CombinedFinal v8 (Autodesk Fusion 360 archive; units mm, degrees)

design "CombinedFinal" references "ThreadCatcher", "Spool", "17HS19-2004S1"
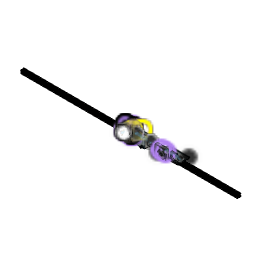
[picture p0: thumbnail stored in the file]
description: Part Number
part number: 5537T11_T-Slotted Framing
part number: 91290A221_Alloy Steel Socket Head Screw
part number: Space Allocation Model
part number: Motor_Bed
base_feature "Base Feature1"
move "Move1"
move "Move2"
move "Move3"
move "Move4"
component_insert "Component Insert1"
work_plane "WorkPlane1" AlongDistance 0
sketch "Stepper2020Side" plane through (0, 0, 0) normal (0, 0, 1) x axis (1, 0, 0)
  line L1 (21.0394, -25.4058) -> (-21.15, -25.4058)
  line L2 (21.0394, 35) -> (21.0394, -25.4058)
  line L3 (-21.15, 35) -> (21.0394, 35)
  line L4 (-21.15, -25.4058) -> (-21.15, 35)
  horizontal L1
  vertical L2
  horizontal L3
  vertical L4
extrude "Extrude2" new body blind 3
extrude "Extrude3" add to an object
extrude "Extrude4" add blind -6
extrude "Extrude5" add sketch "Stepper2020Side" to an object
base_feature "Base Feature1"
move "Move1"
position "Position1"
sketch "StepperSide" plane through (0, -20.4058, 0) normal (0, -1, 0) x axis (1, 0, 0)
  line L1 (16.9429, 17.1363) -> (-16.9429, 17.1363)
  line L2 (20.65, 20.8434) -> (16.9429, 17.1363)
  line L3 (20.65, 54.7291) -> (20.65, 20.8434)
  line L4 (16.9429, 58.4363) -> (20.65, 54.7291)
  line L5 (-16.9429, 58.4363) -> (16.9429, 58.4363)
  line L6 (-20.65, 54.7291) -> (-16.9429, 58.4363)
  line L7 (-20.65, 20.8434) -> (-20.65, 54.7291)
  line L8 (-16.9429, 17.1363) -> (-20.65, 20.8434)
  line L9 (21.15, 54.7291) -> (20.65, 54.7291)
  line L10 (20.65, 20.8434) -> (20.65, 54.7291)
  line L11 (20.65, 20.8434) -> (21.15, 20.8434)
  line L12 (21.15, 54.7291) -> (21.15, 20.8434)
  line L13 (-16.9429, 58.4363) -> (-17.15, 58.9363)
  line L14 (16.9429, 58.4363) -> (-16.9429, 58.4363)
  line L15 (16.9429, 58.4363) -> (16.9429, 58.9363)
  line L16 (-17.15, 58.9363) -> (16.9429, 58.9363)
  line L17 (17.2964, 58.7898) -> (16.9429, 58.4363)
  line L18 (16.9429, 58.4363) -> (16.9429, 58.9363)
  line L19 (17.2964, 58.7898) -> (16.9429, 58.4363)
  line L20 (17.2964, 58.7898) -> (16.9429, 58.4363)
  line L21 (20.65, 54.7291) -> (16.9429, 58.4363)
  line L22 (21.0036, 55.0827) -> (20.65, 54.7291)
  line L23 (17.2964, 58.7898) -> (21.0036, 55.0827)
  line L24 (21.0036, 55.0827) -> (20.65, 54.7291)
  line L25 (21.15, 54.7291) -> (20.65, 54.7291)
  line L26 (20.65, 20.8434) -> (16.9429, 17.1363)
  line L27 (17.2964, 16.7827) -> (16.9429, 17.1363)
  line L28 (21.0036, 20.4898) -> (17.2964, 16.7827)
  line L29 (20.65, 20.8434) -> (21.0036, 20.4898)
  line L30 (16.9429, 17.1363) -> (20.65, 20.8434)
  line L31 (20.65, 20.8434) -> (21.15, 20.8434)
  line L32 (20.65, 20.8434) -> (21.0036, 20.4898)
  line L33 (20.65, 20.8434) -> (21.15, 20.8434)
  line L34 (-16.9429, 17.1363) -> (-16.9429, 16.6363)
  line L35 (16.9429, 16.6363) -> (-16.9429, 16.6363)
  line L36 (16.9429, 16.6363) -> (16.9429, 17.1363)
  line L37 (-16.9429, 17.1363) -> (16.9429, 17.1363)
  line L38 (17.2964, 16.7827) -> (16.9429, 17.1363)
  line L39 (17.2964, 16.7827) -> (16.9429, 17.1363)
  line L40 (16.9429, 16.6363) -> (16.9429, 17.1363)
  line L41 (-21.0036, 20.4898) -> (-20.65, 20.8434)
  line L42 (-17.2964, 16.7827) -> (-21.0036, 20.4898)
  line L43 (-17.2964, 16.7827) -> (-16.9429, 17.1363)
  line L44 (-20.65, 20.8434) -> (-16.9429, 17.1363)
  line L45 (-16.9429, 17.1363) -> (-16.9429, 16.6363)
  line L46 (-17.2964, 16.7827) -> (-16.9429, 17.1363)
  line L47 (-20.65, 54.7291) -> (-21.15, 54.7291)
  line L48 (-21.15, 20.8434) -> (-21.15, 54.7291)
  line L49 (-21.15, 20.8434) -> (-20.65, 20.8434)
  line L50 (-20.65, 54.7291) -> (-20.65, 20.8434)
  line L51 (-21.0036, 20.4898) -> (-20.65, 20.8434)
  line L52 (-21.0036, 20.4898) -> (-20.65, 20.8434)
  line L53 (-21.15, 20.8434) -> (-20.65, 20.8434)
  line L54 (-21.0036, 55.0827) -> (-20.65, 54.7291)
  line L55 (-16.9429, 58.4363) -> (-20.65, 54.7291)
  line L56 (-16.9429, 58.4363) -> (-17.15, 58.9363)
  line L57 (-21.0036, 55.0827) -> (-17.15, 58.9363)
  line L58 (-21.0036, 55.0827) -> (-20.65, 54.7291)
  line L59 (-20.65, 54.7291) -> (-21.15, 54.7291)
  circle C1 centre (0, 37.7863) radius 16
  circle C2 centre (15.5, 53.2863) radius 1.25
  circle C3 centre (-15.5, 53.2863) radius 1.25
  circle C4 centre (-15.5, 22.2863) radius 1.25
  circle C5 centre (15.5, 22.2863) radius 1.25
  arc A1 centre (16.9429, 58.4363) radius 0.5 clockwise from (16.9429, 58.9363) to (17.2964, 58.7898)
  arc A2 centre (20.65, 54.7291) radius 0.5 clockwise from (21.0036, 55.0827) to (21.15, 54.7291)
  arc A3 centre (20.65, 20.8434) radius 0.5 clockwise from (21.15, 20.8434) to (21.0036, 20.4898)
  arc A4 centre (16.9429, 17.1363) radius 0.5 clockwise from (17.2964, 16.7827) to (16.9429, 16.6363)
  arc A5 centre (-16.9429, 17.1363) radius 0.5 clockwise from (-16.9429, 16.6363) to (-17.2964, 16.7827)
  arc A6 centre (-20.65, 20.8434) radius 0.5 clockwise from (-21.0036, 20.4898) to (-21.15, 20.8434)
  arc A7 centre (-20.65, 54.7291) radius 0.5 clockwise from (-21.15, 54.7291) to (-21.0036, 55.0827)
extrude "Extrude7" new body sketch "StepperSide" along normal blind 3
sketch "StepperBottom" plane through (0, 0, 16.6363) normal (0, 0, -1) x axis (1, 0, 0)
  line L1 (16.9429, 20.4058) -> (-16.9429, 20.4058)
  line L2 (16.9429, 23.4058) -> (16.9429, 20.4058)
  line L3 (-16.9429, 23.4058) -> (16.9429, 23.4058)
  line L4 (-16.9429, 20.4058) -> (-16.9429, 23.4058)
  line L5 (16.9429, 20.4058) -> (17.2964, 20.4058)
  line L6 (17.2964, 23.4058) -> (17.2964, 20.4058)
  line L7 (16.9429, 23.4058) -> (17.2964, 23.4058)
  line L8 (16.9429, 20.4058) -> (16.9429, 23.4058)
  line L9 (21.0036, 20.4058) -> (17.2964, 20.4058)
  line L10 (21.0036, 23.4058) -> (21.0036, 20.4058)
  line L11 (17.2964, 23.4058) -> (21.0036, 23.4058)
  line L12 (17.2964, 20.4058) -> (17.2964, 23.4058)
  line L13 (21.0036, 20.4058) -> (21.15, 20.4058)
  line L14 (21.15, 23.4058) -> (21.15, 20.4058)
  line L15 (21.0036, 23.4058) -> (21.15, 23.4058)
  line L16 (21.0036, 20.4058) -> (21.0036, 23.4058)
  line L17 (-17.2964, 20.4058) -> (-16.9429, 20.4058)
  line L18 (-16.9429, 23.4058) -> (-16.9429, 20.4058)
  line L19 (-17.2964, 23.4058) -> (-16.9429, 23.4058)
  line L20 (-17.2964, 20.4058) -> (-17.2964, 23.4058)
  line L21 (-17.2964, 20.4058) -> (-21.0036, 20.4058)
  line L22 (-17.2964, 23.4058) -> (-17.2964, 20.4058)
  line L23 (-21.0036, 23.4058) -> (-17.2964, 23.4058)
  line L24 (-21.0036, 20.4058) -> (-21.0036, 23.4058)
  line L25 (-21.15, 20.4058) -> (-21.0036, 20.4058)
  line L26 (-21.0036, 23.4058) -> (-21.0036, 20.4058)
  line L27 (-21.15, 23.4058) -> (-21.0036, 23.4058)
  line L28 (-21.15, 20.4058) -> (-21.15, 23.4058)
extrude "Extrude8" new body sketch "StepperBottom" to an object Side2Offset 0
extrude "Extrude9" add sketch "StepperBottom" profile of L2 L4 L5 L6 L7 L8 L9 L10 L11 L12 L13 L14 L15 L16 L17 L18 L19 L20 L21 L22 L23 L24 L25 L26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 against normal blind 4.5
extrude "Extrude10" new body sketch "Stepper2020Side" to an object
move "Move2"
position "Position2"
move "Move3"
component_insert "Component Insert2"
position "Position3"
sketch "Sketch8" plane through (0, 0, 16.6363) normal (0, 0, 1) x axis (-1, 0, 0)
  line L1 (-21.0394, 25.4058) -> (21.15, 25.4058)
  line L2 (-21.0394, -32) -> (-21.0394, 25.4058)
  line L3 (21.15, -32) -> (-21.0394, -32)
  line L4 (21.15, 25.4058) -> (21.15, -32)
  circle C1 centre (0, 0) radius 2.5
  point P1 (0, 0)
  point P6 (0, 0)
  coincident P1 P6
  dimension "d24" diameter C1 = 5
position "Position4"
hole "Hole1" HoleDiameter 5.5 TipAngle 118 CBDepth 5 CBDiameter 10
component_insert "Component Insert3"
base_feature "Base Feature1"
base_feature "Base Feature1"
base_feature "Base Feature1"
position "Position5"
sketch "Sketch9" plane through (0, 0, 16.6363) normal (0, 0, 1) x axis (-1, 0, 0)
sketch "Sketch10" plane through (0, 0, 16.6363) normal (0, 0, 1) x axis (-1, 0, 0)
  line L1 (-21.0394, 25.4058) -> (21.15, 25.4058)
  line L2 (21.15, -32) -> (-21.0394, -32)
  line L3 (21.15, 25.4058) -> (21.15, -32)
  line L4 (-40.0394, 25.4058) -> (-21.0394, 25.4058)
  line L5 (-40.0394, 28.4058) -> (-40.0394, 25.4058)
  line L6 (-21.0394, 28.4058) -> (-40.0394, 28.4058)
  line L7 (-21.0394, 25.4058) -> (-21.0394, 28.4058)
  circle C1 centre (0.0553, 0) radius 5
  point P4 (-21.0394, 25.4058)
  point P7 (-21.0394, 25.4058)
  horizontal L4
  vertical L5
  horizontal L6
  vertical L7
  coincident P4 P7
sketch "Sketch12" plane through (0, 0, 0) normal (0, 1, 0) x axis (1, 0, 0)
sketch "Sketch13" plane through (0, -40.1098, 0) normal (0, -1, 0) x axis (1, 0, 0)
  circle C1 centre (69.4158, 38.2803) radius 20.734
  circle C2 centre (69.4158, 38.2803) radius 7
  circle C3 centre (69.4158, 38.2803) radius 6.5
  dimension "d40" diameter C2 = 14
extrude "Extrude11" new body sketch "Sketch13" profile of C2 against normal blind 30 and along normal blind 10
sketch "Sketch15" plane through (0, 0, 10) normal (0, 0, 1) x axis (-1, 0, 0)
  line L1 (-600, -8.25) -> (-600, -3)
  line L2 (619.2, -8.25) -> (-600, -8.25)
  line L3 (619.2, -3) -> (619.2, -8.25)
  line L4 (-600, -3) -> (619.2, -3)
  line L5 (-50, 25) -> (-50, -17)
  line L6 (-117, -17) -> (-50, -17)
  line L7 (-117, 25) -> (-117, -17)
  line L8 (-50, 25) -> (-117, 25)
  line L9 (-50, -17) -> (-50, 25)
  line L10 (-50, 10.1125) -> (-117, 10.1125)
  line L11 (-50, 25) -> (-50, 10.1125)
  line L12 (-117, 25) -> (-50, 25)
  line L13 (-117, 10.1125) -> (-117, 25)
  point P11 (-117, 10.1125)
  point P6 (-50, 25)
  point P7 (-50, -17)
  horizontal L6
  vertical L7
  horizontal L8
  vertical L9
  horizontal L10
  vertical L11
  horizontal L12
  vertical L13
  coincident L7 P11
  dimension "d46" distance P6 P7 = 42
move_face "MoveFace1"
position "Position8"
extrude "Extrude12" new body sketch "Sketch15" profile of L2 L4 L5 to an object
extrude "Extrude14" new body sketch "Sketch15" profile of L2 L4 L5 to an object
extrude "Extrude15" new body sketch "Sketch15" profile of L5 L7 L8 L9 L10 L11 L12 L13 along normal blind 55
position "Position9"
hole "Hole1" HoleDepth 8 HoleDiameter 4.234 TipAngle 118 CBDepth 1 CBDiameter 6.6
sketch "Sketch16" plane through (0, 0, 16.6363) normal (0, 0, 1) x axis (-1, 0, 0)
  line L1 (-187, 10.1125) -> (-120, 10.1125)
  line L2 (-187, -17) -> (-187, 10.1125)
  line L3 (-120, -17) -> (-187, -17)
  line L4 (-120, 10.1125) -> (-120, -17)
  circle C1 centre (-155, 0) radius 2.5
  dimension "d66" diameter C1 = 5
position "Position11"
base_feature "Base Feature1"
move "Move1"
move "Move2"
move "Move3"
move "Move4"
component_insert "Component Insert1"
work_plane "WorkPlane1" AlongDistance 0 named "d1_1"
sketch "Stepper2020Side" plane through (0, 0, 0) normal (0, 0, 1) x axis (1, 0, 0)
  line L1 (21.0394, -25.4058) -> (-21.15, -25.4058)
  line L2 (21.0394, 35) -> (21.0394, -25.4058)
  line L3 (-21.15, 35) -> (21.0394, 35)
  line L4 (-21.15, -25.4058) -> (-21.15, 35)
  horizontal L1
  vertical L2
  horizontal L3
  vertical L4
base_feature "Base Feature1"
position "Position1"
sketch "StepperSide" plane through (0, -20.4058, 0) normal (0, -1, 0) x axis (1, 0, 0)
  line L1 (16.9429, 17.1363) -> (-16.9429, 17.1363)
  line L2 (20.65, 20.8434) -> (16.9429, 17.1363)
  line L3 (20.65, 54.7291) -> (20.65, 20.8434)
  line L4 (16.9429, 58.4363) -> (20.65, 54.7291)
  line L5 (-16.9429, 58.4363) -> (16.9429, 58.4363)
  line L6 (-20.65, 54.7291) -> (-16.9429, 58.4363)
  line L7 (-20.65, 20.8434) -> (-20.65, 54.7291)
  line L8 (-16.9429, 17.1363) -> (-20.65, 20.8434)
  line L9 (21.15, 54.7291) -> (20.65, 54.7291)
  line L10 (20.65, 20.8434) -> (20.65, 54.7291)
  line L11 (20.65, 20.8434) -> (21.15, 20.8434)
  line L12 (21.15, 54.7291) -> (21.15, 20.8434)
  line L13 (-16.9429, 58.4363) -> (-17.15, 58.9363)
  line L14 (16.9429, 58.4363) -> (-16.9429, 58.4363)
  line L15 (16.9429, 58.4363) -> (16.9429, 58.9363)
  line L16 (-17.15, 58.9363) -> (16.9429, 58.9363)
  line L17 (17.2964, 58.7898) -> (16.9429, 58.4363)
  line L18 (16.9429, 58.4363) -> (16.9429, 58.9363)
  line L19 (17.2964, 58.7898) -> (16.9429, 58.4363)
  line L20 (17.2964, 58.7898) -> (16.9429, 58.4363)
  line L21 (20.65, 54.7291) -> (16.9429, 58.4363)
  line L22 (21.0036, 55.0827) -> (20.65, 54.7291)
  line L23 (17.2964, 58.7898) -> (21.0036, 55.0827)
  line L24 (21.0036, 55.0827) -> (20.65, 54.7291)
  line L25 (21.15, 54.7291) -> (20.65, 54.7291)
  line L26 (20.65, 20.8434) -> (16.9429, 17.1363)
  line L27 (17.2964, 16.7827) -> (16.9429, 17.1363)
  line L28 (21.0036, 20.4898) -> (17.2964, 16.7827)
  line L29 (20.65, 20.8434) -> (21.0036, 20.4898)
  line L30 (16.9429, 17.1363) -> (20.65, 20.8434)
  line L31 (20.65, 20.8434) -> (21.15, 20.8434)
  line L32 (20.65, 20.8434) -> (21.0036, 20.4898)
  line L33 (20.65, 20.8434) -> (21.15, 20.8434)
  line L34 (-16.9429, 17.1363) -> (-16.9429, 16.6363)
  line L35 (16.9429, 16.6363) -> (-16.9429, 16.6363)
  line L36 (16.9429, 16.6363) -> (16.9429, 17.1363)
  line L37 (-16.9429, 17.1363) -> (16.9429, 17.1363)
  line L38 (17.2964, 16.7827) -> (16.9429, 17.1363)
  line L39 (17.2964, 16.7827) -> (16.9429, 17.1363)
  line L40 (16.9429, 16.6363) -> (16.9429, 17.1363)
  line L41 (-21.0036, 20.4898) -> (-20.65, 20.8434)
  line L42 (-17.2964, 16.7827) -> (-21.0036, 20.4898)
  line L43 (-17.2964, 16.7827) -> (-16.9429, 17.1363)
  line L44 (-20.65, 20.8434) -> (-16.9429, 17.1363)
  line L45 (-16.9429, 17.1363) -> (-16.9429, 16.6363)
  line L46 (-17.2964, 16.7827) -> (-16.9429, 17.1363)
  line L47 (-20.65, 54.7291) -> (-21.15, 54.7291)
  line L48 (-21.15, 20.8434) -> (-21.15, 54.7291)
  line L49 (-21.15, 20.8434) -> (-20.65, 20.8434)
  line L50 (-20.65, 54.7291) -> (-20.65, 20.8434)
  line L51 (-21.0036, 20.4898) -> (-20.65, 20.8434)
  line L52 (-21.0036, 20.4898) -> (-20.65, 20.8434)
  line L53 (-21.15, 20.8434) -> (-20.65, 20.8434)
  line L54 (-21.0036, 55.0827) -> (-20.65, 54.7291)
  line L55 (-16.9429, 58.4363) -> (-20.65, 54.7291)
  line L56 (-16.9429, 58.4363) -> (-17.15, 58.9363)
  line L57 (-21.0036, 55.0827) -> (-17.15, 58.9363)
  line L58 (-21.0036, 55.0827) -> (-20.65, 54.7291)
  line L59 (-20.65, 54.7291) -> (-21.15, 54.7291)
  circle C1 centre (0, 37.7863) radius 16
  circle C2 centre (15.5, 53.2863) radius 1.25
  circle C3 centre (-15.5, 53.2863) radius 1.25
  circle C4 centre (-15.5, 22.2863) radius 1.25
  circle C5 centre (15.5, 22.2863) radius 1.25
  arc A1 centre (16.9429, 58.4363) radius 0.5 clockwise from (16.9429, 58.9363) to (17.2964, 58.7898)
  arc A2 centre (20.65, 54.7291) radius 0.5 clockwise from (21.0036, 55.0827) to (21.15, 54.7291)
  arc A3 centre (20.65, 20.8434) radius 0.5 clockwise from (21.15, 20.8434) to (21.0036, 20.4898)
  arc A4 centre (16.9429, 17.1363) radius 0.5 clockwise from (17.2964, 16.7827) to (16.9429, 16.6363)
  arc A5 centre (-16.9429, 17.1363) radius 0.5 clockwise from (-16.9429, 16.6363) to (-17.2964, 16.7827)
  arc A6 centre (-20.65, 20.8434) radius 0.5 clockwise from (-21.0036, 20.4898) to (-21.15, 20.8434)
  arc A7 centre (-20.65, 54.7291) radius 0.5 clockwise from (-21.15, 54.7291) to (-21.0036, 55.0827)
extrude "Extrude7" new body sketch "StepperSide" along normal blind 3 named "d14_1"
sketch "StepperBottom" plane through (0, 0, 16.6363) normal (0, 0, -1) x axis (1, 0, 0)
  line L1 (16.9429, 20.4058) -> (-16.9429, 20.4058)
  line L2 (16.9429, 23.4058) -> (16.9429, 20.4058)
  line L3 (-16.9429, 23.4058) -> (16.9429, 23.4058)
  line L4 (-16.9429, 20.4058) -> (-16.9429, 23.4058)
  line L5 (16.9429, 20.4058) -> (17.2964, 20.4058)
  line L6 (17.2964, 23.4058) -> (17.2964, 20.4058)
  line L7 (16.9429, 23.4058) -> (17.2964, 23.4058)
  line L8 (16.9429, 20.4058) -> (16.9429, 23.4058)
  line L9 (21.0036, 20.4058) -> (17.2964, 20.4058)
  line L10 (21.0036, 23.4058) -> (21.0036, 20.4058)
  line L11 (17.2964, 23.4058) -> (21.0036, 23.4058)
  line L12 (17.2964, 20.4058) -> (17.2964, 23.4058)
  line L13 (21.0036, 20.4058) -> (21.15, 20.4058)
  line L14 (21.15, 23.4058) -> (21.15, 20.4058)
  line L15 (21.0036, 23.4058) -> (21.15, 23.4058)
  line L16 (21.0036, 20.4058) -> (21.0036, 23.4058)
  line L17 (-17.2964, 20.4058) -> (-16.9429, 20.4058)
  line L18 (-16.9429, 23.4058) -> (-16.9429, 20.4058)
  line L19 (-17.2964, 23.4058) -> (-16.9429, 23.4058)
  line L20 (-17.2964, 20.4058) -> (-17.2964, 23.4058)
  line L21 (-17.2964, 20.4058) -> (-21.0036, 20.4058)
  line L22 (-17.2964, 23.4058) -> (-17.2964, 20.4058)
  line L23 (-21.0036, 23.4058) -> (-17.2964, 23.4058)
  line L24 (-21.0036, 20.4058) -> (-21.0036, 23.4058)
  line L25 (-21.15, 20.4058) -> (-21.0036, 20.4058)
  line L26 (-21.0036, 23.4058) -> (-21.0036, 20.4058)
  line L27 (-21.15, 23.4058) -> (-21.0036, 23.4058)
  line L28 (-21.15, 20.4058) -> (-21.15, 23.4058)
extrude "Extrude8" new body sketch "StepperBottom" to an object Side2Offset 0 named "d18_1"
extrude "Extrude9" add sketch "StepperBottom" profile of L2 L4 L5 L6 L7 L8 L9 L10 L11 L12 L13 L14 L15 L16 L17 L18 L19 L20 L21 L22 L23 L24 L25 L26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 against normal blind 4.5 named "d20_1"
extrude "Extrude10" new body sketch "Stepper2020Side" to an object
move "Move2"
position "Position2"
move "Move3"
combine "Combine1"
position "Position3"
sketch "Sketch8" plane through (0, 0, 16.6363) normal (0, 0, 1) x axis (-1, 0, 0)
  line L1 (-21.0394, 25.4058) -> (21.15, 25.4058)
  line L2 (-21.0394, -32) -> (-21.0394, 25.4058)
  line L3 (21.15, -32) -> (-21.0394, -32)
  line L4 (21.15, 25.4058) -> (21.15, -32)
  circle C1 centre (0, 0) radius 2.5
  point P1 (0, 0)
  point P6 (0, 0)
  coincident P1 P6
  dimension "d24_1" diameter C1 = 5
position "Position4"
hole "Hole1" HoleDiameter 5.5 named "d25_1" TipAngle 118 named "d26_1" CBDepth 5 named "d27_1" CBDiameter 10 named "d28_1"
sketch "Sketch10" plane through (0, 0, 16.6363) normal (0, 0, 1) x axis (-1, 0, 0)
  line L1 (-21.0394, 25.4058) -> (21.15, 25.4058)
  line L2 (21.15, -32) -> (-21.0394, -32)
  line L3 (21.15, 25.4058) -> (21.15, -32)
  line L4 (-40.0394, 25.4058) -> (-21.0394, 25.4058)
  line L5 (-40.0394, 28.4058) -> (-40.0394, 25.4058)
  line L6 (-21.0394, 28.4058) -> (-40.0394, 28.4058)
  line L7 (-21.0394, 25.4058) -> (-21.0394, 28.4058)
  circle C1 centre (0.0553, 0) radius 5
  point P4 (-21.0394, 25.4058)
  point P7 (-21.0394, 25.4058)
  horizontal L4
  vertical L5
  horizontal L6
  vertical L7
  coincident P4 P7
move_face "MoveFace3"
hole "Hole1" HoleDepth 8 named "d59_1" HoleDiameter 4.234 named "d60_1" TipAngle 118 named "d61_1" CBDepth 1 named "d62_1" CBDiameter 6.6 named "d63_1"
extrude "Extrude4" add of existing geometry blind 3
extrude "Extrude16" new body of existing geometry blind 3 named "d76_1"
sketch "Sketch17" plane through (0, -31.4058, 0) normal (0, -1, 0) x axis (1, 0, 0)
  line L1 (-21.15, 10) -> (-21.15, 54.7291)
  line L2 (21.15, 10) -> (-21.15, 10)
  line L3 (21.15, 54.7291) -> (21.15, 10)
  line L4 (17.2964, 58.7898) -> (21.0036, 55.0827)
  line L5 (-17.15, 58.9363) -> (16.9429, 58.9363)
  line L6 (-21.0036, 55.0827) -> (-17.15, 58.9363)
  arc A1 centre (20.65, 54.7291) radius 0.5 clockwise from (21.0036, 55.0827) to (21.15, 54.7291)
  arc A2 centre (16.9429, 58.4363) radius 0.5 clockwise from (16.9429, 58.9363) to (17.2964, 58.7898)
  arc A3 centre (-20.65, 54.7291) radius 0.5 clockwise from (-21.15, 54.7291) to (-21.0036, 55.0827)
  circle C1 centre (0, 37.7863) radius 16
  circle C2 centre (-15.5, 22.2863) radius 1.25
  circle C3 centre (15.5, 22.2863) radius 1.25
  circle C4 centre (-15.5, 53.2863) radius 1.25
  circle C5 centre (15.5, 53.2863) radius 1.25
hole "Hole2" HoleDepth 6 named "d78_1" HoleDiameter 2.529 named "d79_1" TipAngle 118 named "d80_1" CBDepth 1 named "d81_1" CBDiameter 2.782 named "d82_1"
combine "Combine1"
hole "Hole2" HoleDepth 10 named "d85_1" HoleDiameter 5.5 named "d86_1" TipAngle 118 named "d87_1" CBDepth 5 named "d88_1" CBDiameter 10 named "d89_1"
sketch "Sketch18" plane through (0, -31.4058, 0) normal (0, -1, 0) x axis (1, 0, 0)
  line L1 (-21.15, 10) -> (-21.15, 54.7291)
  line L2 (21.15, 10) -> (-21.15, 10)
  line L3 (21.15, 54.7291) -> (21.15, 10)
  line L4 (17.2964, 58.7898) -> (21.0036, 55.0827)
  line L5 (-17.15, 58.9363) -> (16.9429, 58.9363)
  line L6 (-21.0036, 55.0827) -> (-17.15, 58.9363)
  circle C1 centre (15.5, 22.2863) radius 1.391
  circle C2 centre (-15.5, 53.2863) radius 1.391
  circle C3 centre (15.5, 53.2863) radius 1.391
  circle C4 centre (-15.5, 22.2863) radius 1.391
  arc A1 centre (20.65, 54.7291) radius 0.5 clockwise from (21.0036, 55.0827) to (21.15, 54.7291)
  arc A2 centre (16.9429, 58.4363) radius 0.5 clockwise from (16.9429, 58.9363) to (17.2964, 58.7898)
  arc A3 centre (-20.65, 54.7291) radius 0.5 clockwise from (-21.15, 54.7291) to (-21.0036, 55.0827)
  circle C5 centre (0, 37.7863) radius 16
extrude "Extrude1" add sketch "Sketch10" profile of L4 L5 L6 L7 to an object
move_face "MoveFace1"
extrude "Extrude2" add of existing geometry blind 20
move_face "MoveFace2"
sketch "Sketch11" plane through (0, -28.4058, 0) normal (0, -1, 0) x axis (1, 0, 0)
  line L1 (17.2964, 58.7898) -> (21.0036, 55.0827)
  line L2 (-17.15, 58.9363) -> (16.9429, 58.9363)
  line L3 (-21.0036, 55.0827) -> (-17.15, 58.9363)
  line L4 (-21.15, 10) -> (-21.15, 54.7291)
  line L5 (99.0394, 10) -> (-21.15, 10)
  line L6 (99.0394, 78.9363) -> (99.0394, 10)
  line L7 (21.15, 78.9363) -> (99.0394, 78.9363)
  line L8 (21.15, 54.7291) -> (21.15, 78.9363)
  circle C1 centre (0, 37.7863) radius 16
  circle C2 centre (-15.5, 22.2863) radius 1.25
  circle C3 centre (15.5, 22.2863) radius 1.25
  circle C4 centre (-15.5, 53.2863) radius 1.25
  circle C5 centre (15.5, 53.2863) radius 1.25
  arc A1 centre (20.65, 54.7291) radius 0.5 clockwise from (21.0036, 55.0827) to (21.15, 54.7291)
  arc A2 centre (16.9429, 58.4363) radius 0.5 clockwise from (16.9429, 58.9363) to (17.2964, 58.7898)
  arc A3 centre (-20.65, 54.7291) radius 0.5 clockwise from (-21.15, 54.7291) to (-21.0036, 55.0827)
  circle C6 centre (49.4158, 53.2803) radius 2.5
extrude "Extrude3" add sketch "Sketch11" profile of C6 along normal blind 30
combine "Combine1"
component_from_bodies "Body->Comp1"
component_from_bodies "Body->Comp2"
sketch "Sketch17" plane through (0, -40.1014, 0) normal (0, -1, 0) x axis (1, 0, 0)
  circle C1 centre (71.4199, 39.5957) radius 20.734
  circle C2 centre (71.4199, 39.5957) radius 6.5
sketch "Sketch1" plane through (0, 0, 19) normal (0, 0, 1) x axis (-1, 0, 0)
  line L1 (-99.1722, 32.9222) -> (-99.1722, 23.9222)
  line L2 (-105.1722, 36.9222) -> (-103.1722, 36.9222)
  line L3 (-109.1722, 23.9222) -> (-109.1722, 32.9222)
  line L4 (-99.1722, 23.9222) -> (-109.1722, 23.9222)
  line L5 (-117, 10.1125) -> (-117, 25)
  line L6 (-50, 10.1125) -> (-117, 10.1125)
  line L7 (-50, 25) -> (-50, 10.1125)
  line L8 (-117, 25) -> (-50, 25)
  circle C1 centre (-104.1722, 31.4222) radius 2.5
  arc A1 centre (-103.1722, 32.9222) radius 4 clockwise from (-103.1722, 36.9222) to (-99.1722, 32.9222)
  arc A2 centre (-105.1722, 32.9222) radius 4 clockwise from (-109.1722, 32.9222) to (-105.1722, 36.9222)
extrude "Extrude1" add sketch "Sketch1" profile of C1 L1 A1 L2 A2 L3 L8 to an object
sketch "Sketch2" plane through (0, -25, 0) normal (0, -1, 0) x axis (1, 0, 0)
  line L1 (109.1722, 15) -> (109.1722, 19)
  line L2 (99.1722, 15) -> (109.1722, 15)
  line L3 (99.1722, 19) -> (99.1722, 15)
  line L4 (109.1722, 19) -> (99.1722, 19)
  line L5 (117, 10) -> (50, 10)
  line L6 (117, 65) -> (117, 10)
  line L7 (50, 65) -> (117, 65)
  line L8 (50, 10) -> (50, 65)
  circle C1 centre (71.4199, 39.5957) radius 2.85
  circle C2 centre (71.4199, 39.5957) radius 7.7
  dimension "d78" diameter C1 = 5.7
extrude "Extrude2" cut sketch "Sketch2" profile of C1 against normal blind 64
position "Position12"
sketch "Sketch3" plane through (0, 0, 16.6363) normal (0, 0, 1) x axis (-1, 0, 0)
  line L1 (-50, 10.1125) -> (-50, -17)
  line L2 (-117, 10.1125) -> (-50, 10.1125)
  line L3 (-117, -17) -> (-117, 10.1125)
  line L4 (-50, -17) -> (-117, -17)
extrude "Extrude3" add sketch "Sketch3" to an object
position "Position13"
move "Move1"
extrude "Extrude16" new body of existing geometry to an object
extrude "Extrude4" add of existing geometry blind 18
sketch "Sketch18" plane through (0, 0, 16.6363) normal (0, 0, 1) x axis (-1, 0, 0)
  line L1 (-50, 33.1125) -> (-50, -12)
  line L2 (-117, 33.1125) -> (-50, 33.1125)
  line L3 (-117, -12) -> (-117, 33.1125)
  line L4 (-50, -12) -> (-117, -12)
  circle C1 centre (-85, 0) radius 2.5
  circle C2 centre (-85, 0) radius 2.5
  circle C3 centre (-66, 0) radius 2.5
  circle C4 centre (-104, 0) radius 2.5
  dimension "d87" diameter C1 = 5
  dimension "d88" diameter C2 = 5
  dimension "d89" diameter C3 = 5
  dimension "d90" diameter C4 = 5
hole "Hole1" HoleDepth 8 HoleDiameter 3.4 TipAngle 118 CBDepth 3.4 CBDiameter 6.5
copy_paste_bodies "CopyPasteBodies1"
move "Move4"
sketch "Sketch19" plane through (0, 0, 19) normal (0, 0, 1) x axis (-1, 0, 0)
  line L1 (-169.1722, 55.9222) -> (-169.1722, 48)
  line L2 (-175.1722, 59.9222) -> (-173.1722, 59.9222)
  line L3 (-179.1722, 48) -> (-179.1722, 55.9222)
  line L4 (-169.1722, 48) -> (-179.1722, 48)
  circle C1 centre (-174.1722, 54.4222) radius 2.5
  arc A1 centre (-173.1722, 55.9222) radius 4 clockwise from (-173.1722, 59.9222) to (-169.1722, 55.9222)
  arc A2 centre (-175.1722, 55.9222) radius 4 clockwise from (-179.1722, 55.9222) to (-175.1722, 59.9222)
extrude "Extrude17" new body sketch "Sketch19" against normal blind 4
move "Move5"
move "Move1"
move "Move6"
split "Split1"
remove_body "RemoveBody3"
sketch "Sketch20" plane through (0, -48, 0) normal (0, -1, 0) x axis (1, 0, 0)
  line L1 (109.1722, 15) -> (109.1722, 19)
  line L2 (99.1722, 15) -> (109.1722, 15)
  line L3 (99.1722, 19) -> (99.1722, 15)
  line L4 (109.1722, 19) -> (99.1722, 19)
  line L5 (117, 10) -> (50, 10)
  line L6 (117, 65) -> (117, 10)
  line L7 (50, 65) -> (117, 65)
  line L8 (50, 10) -> (50, 65)
  circle C1 centre (71.4199, 39.5957) radius 2.85
copy_paste_bodies "CopyPasteBodies2"
move "Move7"
move "Move8"
move "Move9"
move "Move10"
sketch "Sketch21" plane through (0, -33.1125, 0) normal (0, 1, 0) x axis (-1, 0, 0)
  line L1 (-175, 16.6363) -> (-242, 16.6363)
  line L2 (-175, 65) -> (-175, 16.6363)
  line L3 (-242, 65) -> (-175, 65)
  line L4 (-242, 16.6363) -> (-242, 65)
  circle C1 centre (-196.4199, 39.5957) radius 2.85
  circle C2 centre (-220.5801, 39.5957) radius 2.85
  circle C3 centre (-196.4199, 39.5957) radius 2.85
extrude "Extrude18" cut sketch "Sketch21" profile of C2 against normal blind 35
copy_paste_bodies "CopyPasteBodies3"
move "Move11"
move "Move12"
move "Move13"
move "Move14"
move "Move15"
move "Move16"
move "Move17"
move "Move18"
move "Move19"
extrude "Extrude19" add sketch "Sketch21" profile of C1 C3 to an object
move "Move20"
extrude "Extrude20" add of existing geometry blind 1.5
combine "Combine5"
fillet "Fillet1" radius 1.5
fillet "Fillet1" radius 1.5
sketch "Sketch23" plane through (0, 0, 0) normal (0, 0, 1) x axis (1, 0, 0)
move_face "MoveFace1"
move "Move1"
move "Move2"
move "Move3"
move "Move4"
position "Position14"
combine "Combine1"
move "Move4"
move "Move5"
sketch "Sketch24" plane through (0, 0, 16.6363) normal (0, 0, 1) x axis (-1, 0, 0)
  line L1 (-45, 33.1125) -> (-45, -12)
  line L2 (-117, 33.1125) -> (-45, 33.1125)
  line L3 (-117, -12) -> (-117, 33.1125)
  line L4 (-45, -12) -> (-117, -12)
  line L5 (-3, 33.1125) -> (-117, 33.1125)
  line L6 (-3, -30.41) -> (-3, 33.1125)
  line L7 (-117, -30.41) -> (-3, -30.41)
  line L8 (-117, 33.1125) -> (-117, -30.41)
  circle C1 centre (-85, 0) radius 3.25
  circle C2 centre (-104, 0) radius 3.25
  circle C3 centre (-66, 0) radius 3.25
  point P7 (-117, 33.1125)
  point P9 (-117, 33.1125)
  horizontal L5
  vertical L6
  horizontal L7
  vertical L8
  coincident P7 P9
extrude "Extrude21" new body sketch "Sketch24" to an object
copy_paste_bodies "CopyPasteBodies4"
move "Move21"
hole "Hole3" HoleDepth 15 HoleDiameter 3.4 TipAngle 118 CBDepth 3.4 CBDiameter 6.5
hole "Hole4" HoleDepth 15 HoleDiameter 3.4 TipAngle 118 CBDepth 3.4 CBDiameter 6.5
hole "Hole5" HoleDepth 15 HoleDiameter 3.4 TipAngle 118 CBDepth 3.4 CBDiameter 6.5
hole "Hole6" HoleDepth 15 HoleDiameter 3.4 TipAngle 118 CBDepth 3.4 CBDiameter 6.5
move "Move22"
extrude "Extrude22" add of existing geometry blind 4
hole "Hole2" HoleDepth 15 HoleDiameter 3.4 TipAngle 118 CBDepth 3.4 CBDiameter 6.5
hole "Hole3" HoleDepth 15 HoleDiameter 3.4 TipAngle 118 CBDepth 3.4 CBDiameter 6.5
hole "Hole4" HoleDepth 15 HoleDiameter 3.4 TipAngle 118 CBDepth 3.4 CBDiameter 6.5
hole "Hole5" HoleDepth 15 HoleDiameter 3.4 TipAngle 118 CBDepth 3.4 CBDiameter 6.5
sketch "Sketch25" plane through (0, 0, 16.6363) normal (0, 0, 1) x axis (-1, 0, 0)
  line L1 (-3, -30.41) -> (-117, -30.41)
  line L2 (-3, 33.1125) -> (-3, -30.41)
  line L3 (-117, 33.1125) -> (-3, 33.1125)
  line L4 (-117, -30.41) -> (-117, 33.1125)
  line L5 (-24, -4.35) -> (-104, -4.35)
  line L6 (-104, 4.35) -> (-24, 4.35)
  line L7 (-24, 0) -> (-104, 0)
  arc A1 centre (-24, 0) radius 4.35 clockwise from (-24, 4.35) to (-24, -4.35)
  arc A2 centre (-104, 0) radius 4.35 clockwise from (-104, -4.35) to (-104, 4.35)
  tangent L5 A1
  tangent A1 L6
  parallel L5 L6
  tangent L6 A2
  tangent L5 A2
  parallel L1 L7
  dimension "d154" diameter A1 = 8.7
combine "Combine1"
combine "Combine2"
extrude "Extrude5" cut sketch "Sketch25" profile of L5 A1 L6 A2 against normal blind 10
fillet "Fillet2" radius 1.5
fillet "Fillet3" radius 6
split "Split1"
combine "Combine3"
sketch "Sketch26" plane through (0, 0, 16.6363) normal (0, 0, 1) x axis (-1, 0, 0)
  line L1 (-175, 33.1125) -> (-175, -12)
  line L2 (-246, 33.1125) -> (-175, 33.1125)
  line L3 (-246, 33) -> (-246, 33.1125)
  line L4 (-246, 27) -> (-246, 33)
  line L5 (-288.1894, 27) -> (-246, 27)
  line L6 (-288.1894, -30.4058) -> (-288.1894, 27)
  line L7 (-246, -30.4058) -> (-288.1894, -30.4058)
  line L8 (-246, -12) -> (-246, -30.4058)
  line L9 (-175, -12) -> (-246, -12)
  line L10 (-175, -30.4058) -> (-288.1894, -30.4058)
  line L11 (-175, 33.1125) -> (-175, -30.4058)
  line L12 (-288.1894, 33.1125) -> (-175, 33.1125)
  line L13 (-288.1894, -30.4058) -> (-288.1894, 33.1125)
  line L14 (-267.6514, 4.35) -> (-191, 4.35)
  line L15 (-191, -4.35) -> (-267.6514, -4.35)
  line L16 (-267.6514, 0) -> (-191, 0)
  arc A1 centre (-267.6514, 0) radius 4.35 clockwise from (-267.6514, -4.35) to (-267.6514, 4.35)
  arc A2 centre (-191, 0) radius 4.35 clockwise from (-191, 4.35) to (-191, -4.35)
  point P3 (-175, 33.1125)
  point P13 (-175, 33.1125)
  point P8 (-288.1894, -30.4058)
  point P11 (-288.1894, -30.4058)
  horizontal L10
  vertical L11
  horizontal L12
  vertical L13
  coincident P3 P13
  coincident P8 P11
  tangent L14 A1
  tangent A1 L15
  parallel L14 L15
  tangent L15 A2
  tangent L14 A2
  horizontal L16
  dimension "d169" diameter A1 = 8.7
extrude "Extrude24" new body sketch "Sketch26" profile of L1 L2 L3 L4 L5 L6 L7 L8 L9 L10 L11 L12 L13 to an object
combine "Combine6"
fillet "Fillet2" radius 5.5 3
split "Split2"
split "Split3"
remove_body "RemoveBody4"
combine "Combine7"
extrude "Extrude25" cut sketch "Sketch26" profile of L14 A1 L15 A2 against normal blind 15
combine "Combine8"
extrude "Extrude26" cut sketch "Sketch26" profile of L14 A1 L15 A2 against normal blind 15
extrude "Extrude27" cut of existing geometry blind -5
extrude "Extrude6" cut of existing geometry blind -5
extrude "Extrude7" cut of existing geometry blind -5
extrude "Extrude28" cut of existing geometry blind -5
fillet "Fillet4" radius 3.5
extrude "Extrude23" cut sketch "Sketch25" profile of L5 A1 L6 A2 against normal blind 9
combine "Combine2"
sketch "Sketch22" plane through (0, 0, 10) normal (0, 0, 1) x axis (-1, 0, 0)
  line L1 (-600, 3) -> (-600, 8.25)
  line L2 (619.2, 3) -> (-600, 3)
  line L3 (619.2, 8.25) -> (619.2, 3)
  line L4 (-600, 8.25) -> (619.2, 8.25)
position "Position6"
sketch "Sketch11" plane through (0, -28.4058, 0) normal (0, -1, 0) x axis (1, 0, 0)
  line L1 (17.2964, 58.7898) -> (21.0036, 55.0827)
  line L2 (-17.15, 58.9363) -> (16.9429, 58.9363)
  line L3 (-21.0036, 55.0827) -> (-17.15, 58.9363)
  line L4 (-21.15, 10) -> (-21.15, 54.7291)
  line L5 (99.0394, 10) -> (-21.15, 10)
  line L6 (99.0394, 78.9363) -> (99.0394, 10)
  line L7 (21.15, 78.9363) -> (99.0394, 78.9363)
  line L8 (21.15, 54.7291) -> (21.15, 78.9363)
  circle C1 centre (0, 37.7863) radius 16
  circle C2 centre (-15.5, 22.2863) radius 1.25
  circle C3 centre (15.5, 22.2863) radius 1.25
  circle C4 centre (-15.5, 53.2863) radius 1.25
  circle C5 centre (15.5, 53.2863) radius 1.25
  arc A1 centre (20.65, 54.7291) radius 0.5 clockwise from (21.0036, 55.0827) to (21.15, 54.7291)
  arc A2 centre (16.9429, 58.4363) radius 0.5 clockwise from (16.9429, 58.9363) to (17.2964, 58.7898)
  arc A3 centre (-20.65, 54.7291) radius 0.5 clockwise from (-21.15, 54.7291) to (-21.0036, 55.0827)
  circle C6 centre (49.4158, 53.2803) radius 2.5
position "Position7"
combine "Combine1"
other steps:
base_feature "Base Feature1"
extrude "Extrude2" cut of existing geometry blind -5
hole "Hole1" HoleDepth 10 named "d90_1" HoleDiameter 5.5 named "d91_1" TipAngle 118 named "d92_1" CBDepth 5 named "d93_1" CBDiameter 10 named "d94_1"
base_feature "Base Feature1"
hole "Hole1" HoleDiameter 5.5 TipAngle 118 CBDepth 5 CBDiameter 10
thread "Thread1" ThreadOffset 0 named "d64_1" ThreadDepth 7.4 named "d65_1"
thread "Thread2" ThreadOffset 0 named "d83_1" ThreadDepth 7.4 named "d84_1"
thread "Thread1" ThreadOffset 0 ThreadDepth 7.4
base_feature "Base Feature1"
base_feature "Base Feature2"
base_feature "Base Feature3"
base_feature "Base Feature4"
create_component "CreateComponent1"
create_component "CreateComponent2"
create_component "CreateComponent6"
create_component "CreateComponent8"
remove_body "RemoveBody1"
create_component "CreateComponent9"
remove_body "RemoveBody2"
create_component "CreateComponent1"
create_component "CreateComponent2"
create_component "CreateComponent11"
create_component "CreateComponent1"
create_component "CreateComponent2"
create_component "CreateComponent4"
create_component "CreateComponent6"
create_component "CreateComponent8"
create_component "CreateComponent12"

design "ThreadCatcher"
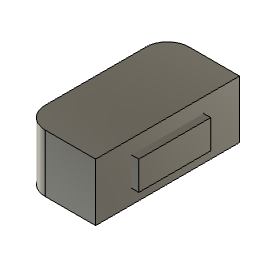
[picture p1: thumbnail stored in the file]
description: Part Number
part number: Space Allocation Model
part number: Motor_Bed

design "17HS19-2004S1"
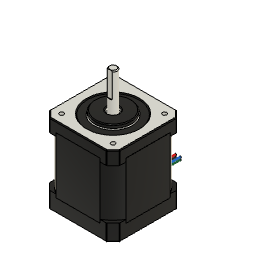
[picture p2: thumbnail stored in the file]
description: STEP AP214
part number: 17HS19-2004S1

design "Spool" references "17HS19-2004S1"
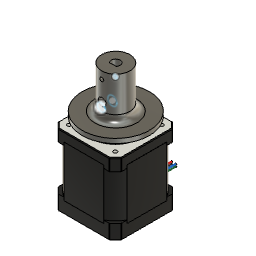
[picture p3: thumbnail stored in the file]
description: STEP AP214
part number: 17HS19-2004S1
